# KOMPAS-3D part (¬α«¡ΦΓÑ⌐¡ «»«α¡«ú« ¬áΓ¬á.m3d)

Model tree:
1. Эскиз:1
2. Операция выдавливания:1
     Расстояние 1 = 1.5
3. Скругление:1
     Радиус = 1
4. Эскиз:2
5. Операция выдавливания:2
     Расстояние 1 = 1.5
6. Скругление:3
     Радиус = 0.2
7. Эскиз:3
8. Вырезать элемент выдавливания:1
     Расстояние 1 = 1.5; Угол 1 = 8
9. Скругление:4
     Радиус = 0.1
10. Эскиз:4
11. Отверстие:1
12. Скругление:5
     Радиус = 0.1
13. Эскиз:5
14. Операция выдавливания:3
     Расстояние 1 = 0.8
15. Скругление:6
     Радиус = 0.1

Referenced files in C:\Program Files\ASCON\KOMPAS-3D V13 Home\Sys\: holelib.lfr
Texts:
  кронштейн опорного катка
  Сплав АЛ8  ГОСТ 1583-93
  Отверстие 01
  (вариант 1)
